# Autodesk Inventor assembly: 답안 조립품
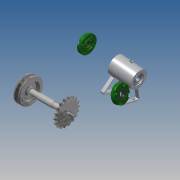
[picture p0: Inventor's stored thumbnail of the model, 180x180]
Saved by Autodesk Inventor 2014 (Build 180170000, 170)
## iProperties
Created: 2016-03
Part Number: 답안 조립품
Document SubType Name: Assembly
Designer: 406-003
Author: 406-003
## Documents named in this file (9)
- C:\Users\406-003\Desktop\460307V1006\답안 조립품.iam
- C:\Users\406-003\Desktop\460307V1006\본체1.ipt
- C:\Users\406-003\Desktop\460307V1006\V벨트풀리.ipt
- C:\Users\406-003\Desktop\460307V1006\스프로킷.ipt
- C:\Users\406-003\Desktop\460307V1006\축.ipt
- C:\Users\406-003\Desktop\460307V1006\베어링 15 x 32 x 9.ipt
- C:\Users\406-003\Desktop\460307V1006\오일 실 15 25 7.ipt
- C:\Users\406-003\Desktop\460307V1006\커버.ipt
- C:\Users\406-003\Desktop\460307V1006\키 3 x 3 x 12.ipt
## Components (3 placed, 2 different names)
1. V벨트풀리:1 — 각도:3
2. KS B 2023 6002 - 15 x 32 x 9:1
3. KS B 2023 6002 - 15 x 32 x 9:2
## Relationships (1: Angle 1)
- 각도:3 [Angle]: V벨트풀리:1
## Named parameters: d5_d4 = 0
